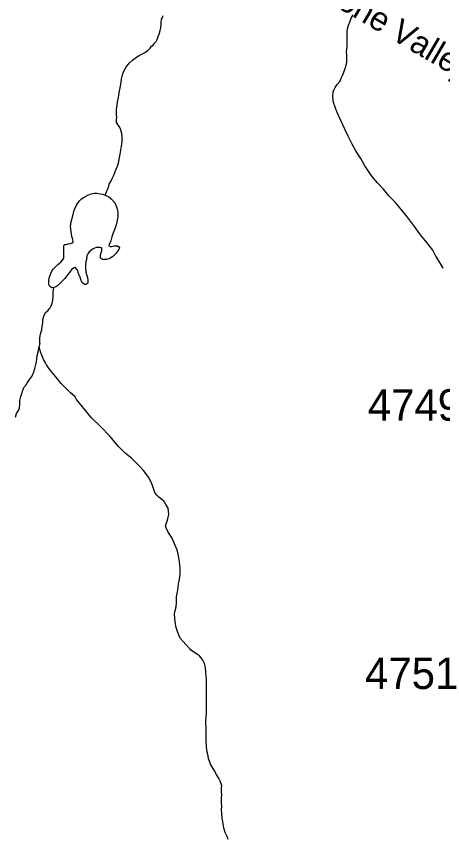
# Model space of a CAD drawing. Extents: x 2001466 to 2224147, y 644118 to 847247.
# Drawn here: x 2068297 to 2069996, y 672647 to 675928 of the extents above; entities that cross this region are included whole.
import ezdxf

# ---------------------------------------------------------------- set-up
doc = ezdxf.new("R2010")
doc.units = 0
for name, color, linetype in [('Exist Hydrographic Misc Water Feature', 7, 'Continuous'), ('Exist Road Non-System Type 51 Label', 7, 'Continuous'), ('Exist Road Secondary Type 51 Number Label', 7, 'Continuous')]:
    doc.layers.add(name, color=color, linetype=linetype)

msp = doc.modelspace()

# ---------------------------------------------------------------- linework, layer by layer
at = {"layer": 'Exist Hydrographic Misc Water Feature'}
msp.add_line((2068389.9, 674624.9), (2068387.2, 674613.2), dxfattribs=at)
for points in [[(2069998.9, 674924.2), (2069985, 674947.7), (2069969, 674972), (2069956.9, 674995.8), (2069938.9, 675020), (2069908.5, 675057.9), (2069880.4, 675095.8), (2069856.4, 675127.8), (2069834.3, 675155.5), (2069806.6, 675187.8), (2069782.4, 675213.3), (2069760.3, 675239.4), (2069736.7, 675265.3), (2069714.1, 675291.4), (2069700.4, 675311.3), (2069686.2, 675333.3), (2069670, 675361.3), (2069652.2, 675389.2), (2069636, 675419.2), (2069620, 675451.3), (2069606.1, 675478.9), (2069590.1, 675513), (2069575.9, 675545.2), (2069567.9, 675567.1), (2069561.6, 675585), (2069558.1, 675609.1), (2069559.7, 675627.1), (2069563.8, 675637), (2069567.7, 675644.9), (2069575.7, 675657.1), (2069585.8, 675669), (2069593.5, 675685.2), (2069597.9, 675695.2), (2069607.7, 675721.2), (2069613.8, 675745), (2069613.8, 675755.2), (2069613.8, 675773), (2069613.4, 675788.9), (2069615.5, 675808.9), (2069615.5, 675827.1), (2069615.1, 675845), (2069615.5, 675857.2), (2069615.3, 675868.9), (2069617.5, 675879.1), (2069621, 675893.2), (2069627.2, 675908.9), (2069631.3, 675921.3), (2069639.1, 675935.1)], [(2068698.5, 675501.3), (2068696, 675505.3), (2068696, 675515.4), (2068696.4, 675527.6), (2068696, 675535.3), (2068696, 675545.5), (2068696, 675555.2), (2068696.2, 675559.2), (2068698.1, 675573.5), (2068700.1, 675587.5), (2068703.8, 675605.5), (2068706.1, 675623.4), (2068709.8, 675643.5), (2068713.9, 675665.3), (2068715.7, 675679.6), (2068719.8, 675695.6), (2068723.9, 675707.5), (2068729.7, 675719.6), (2068735.6, 675729.3), (2068747.7, 675743.3), (2068759.6, 675753.7), (2068769.9, 675761.4), (2068783.8, 675771.4), (2068799.6, 675779.6), (2068811.7, 675785.5), (2068821.5, 675793.7), (2068829.7, 675801.4), (2068835.7, 675809.4), (2068841.4, 675813.8), (2068847.4, 675821.4), (2068853.5, 675827.8), (2068857.4, 675835.7), (2068861.5, 675847.7), (2068865.8, 675857.6), (2068869.3, 675871.7), (2068871.4, 675877.9), (2068873.6, 675891.7), (2068873.4, 675903.5), (2068875.5, 675917.8), (2068877.3, 675921.5), (2068881.4, 675931.5)], [(2068650.7, 675215.3), (2068658.7, 675235.5), (2068660.6, 675241.4), (2068664.9, 675251.3), (2068666.7, 675259.5), (2068672.7, 675269.6), (2068678.8, 675281.6), (2068684.6, 675295.4), (2068688.9, 675305.7), (2068694.4, 675319.4), (2068700.5, 675335.5), (2068704.6, 675349.5), (2068706.7, 675359.3), (2068710.4, 675379.4), (2068714.5, 675403.6), (2068716.1, 675411.4), (2068718.4, 675429.3), (2068718.4, 675439.5), (2068718.4, 675449.6), (2068716.3, 675461.2), (2068714.3, 675469.3), (2068712.2, 675477.3), (2068706.3, 675489.5), (2068698.5, 675501.3)], [(2068445.3, 674847.3), (2068437.7, 674846.9), (2068433.4, 674849.1), (2068429.3, 674851), (2068425.2, 674859.3), (2068425.4, 674865), (2068425.4, 674875.1), (2068427.4, 674884.9), (2068429.3, 674893.2), (2068433.4, 674903), (2068437.3, 674913), (2068443.2, 674921), (2068451.4, 674929.1), (2068457.4, 674935.1), (2068463.1, 674941.1), (2068469.2, 674945.1), (2068472.9, 674949), (2068479.1, 674955), (2068483, 674961.2), (2068485.4, 674965), (2068485, 674971.1), (2068485.4, 674983.2), (2068485.2, 674989.3), (2068485.2, 674997), (2068485.2, 675003.1), (2068485.2, 675007.2), (2068485.4, 675011.2), (2068485.2, 675015.3), (2068489.3, 675019.1), (2068495.3, 675019), (2068503.3, 675021.1), (2068513.3, 675023.2), (2068519.1, 675025.1), (2068522.8, 675029), (2068521.1, 675039), (2068517, 675051), (2068515, 675071.2), (2068512.7, 675091.4), (2068515, 675109.3), (2068521.1, 675133.1), (2068526.9, 675155.4), (2068536.7, 675179), (2068547, 675191.3), (2068556.6, 675201.1), (2068567.1, 675207.3), (2068580.6, 675215.3), (2068594.7, 675221.3), (2068606.6, 675223.2), (2068618.5, 675223.4), (2068630.6, 675221.6), (2068640.9, 675219.2), (2068650.7, 675215.3)], [(2068650.7, 675215.3), (2068664.7, 675209.5), (2068674.9, 675201.5), (2068688.7, 675185.6), (2068695, 675169.6), (2068699.1, 675155.6), (2068700.8, 675145.6), (2068700.8, 675127.4), (2068698.7, 675115.5), (2068695.2, 675101.5), (2068688.9, 675081.7), (2068680.9, 675061.4), (2068677.2, 675049.5), (2068673.1, 675033.4), (2068666.9, 675019.4), (2068665.1, 675013.5), (2068671.2, 675011.4), (2068677.2, 675011.3), (2068686.8, 675013.5), (2068695, 675013.5), (2068699.1, 675013.7), (2068704.9, 675009.6), (2068707.1, 675005.6), (2068704.9, 674999.4), (2068701, 674993.5), (2068693.4, 674983.3), (2068689.3, 674979.5), (2068681.1, 674971.4), (2068674.9, 674967.4), (2068669.2, 674963.4), (2068655.2, 674959.5), (2068647.2, 674959.5), (2068639.2, 674959.5), (2068635.1, 674961.3), (2068631.2, 674965.5), (2068631.2, 674973.3), (2068632.9, 674983.5), (2068637.2, 674993.5), (2068636.8, 675001.6), (2068635.3, 675005.5), (2068628.8, 675007.3), (2068622.8, 675007.4), (2068614.8, 675007.4), (2068603.1, 675001.4), (2068597, 674997.5), (2068587.2, 674989.3), (2068581.2, 674981.3), (2068577.3, 674973.3), (2068575.5, 674959.4), (2068573.2, 674951.2), (2068571.4, 674937.3), (2068571.4, 674925.5), (2068573.4, 674909.4), (2068575.3, 674899.4), (2068579.6, 674887.4), (2068581.4, 674875.4), (2068581.2, 674871.4), (2068581.2, 674867.3), (2068579.4, 674863.5), (2068573.6, 674859.1), (2068567.7, 674859.2), (2068561.3, 674865.4), (2068557.4, 674869.3), (2068553.5, 674879.2), (2068551.3, 674889.3), (2068547.2, 674897.1), (2068543.3, 674907.1), (2068541.2, 674915.1), (2068537.3, 674919.3), (2068533.2, 674925.2), (2068529.1, 674927.1), (2068523.4, 674925.1), (2068517.2, 674921.2), (2068507.6, 674907.2), (2068501.2, 674899.3), (2068493, 674889.2), (2068489.1, 674883.3), (2068483.4, 674877.2), (2068475.4, 674869.1), (2068467.2, 674861), (2068461.5, 674855), (2068453.7, 674850.9), (2068445.3, 674847.3)], [(2068389.9, 674624.9), (2068390.1, 674633), (2068389.9, 674645.2), (2068391.5, 674655.1), (2068393.6, 674666.9), (2068397.7, 674679.3), (2068399.7, 674693.2), (2068401.6, 674705.1), (2068401.8, 674713.2), (2068403.6, 674725.1), (2068407.7, 674737), (2068413.7, 674749.1), (2068421.5, 674755.2), (2068427.4, 674763.2), (2068431.5, 674767), (2068435.4, 674775), (2068439.3, 674783.3), (2068441.6, 674797.2), (2068443.4, 674813.1), (2068443.6, 674828.9), (2068445.3, 674847.3)], [(2068304.6, 674356.8), (2068308.3, 674366.8), (2068310.1, 674383.1), (2068310.3, 674396.9), (2068314.2, 674412.9), (2068317.9, 674424.9), (2068322.4, 674438.9), (2068326.1, 674448.8), (2068336.4, 674461.1), (2068339.9, 674467), (2068346.2, 674477), (2068356.3, 674490.9), (2068362, 674501), (2068365.9, 674510.9), (2068370, 674524.9), (2068374.3, 674540.9), (2068375.9, 674551.2), (2068377.8, 674565.1), (2068379.8, 674577), (2068384.2, 674597), (2068387.2, 674613.2)], [(2068535.9, 674401.2), (2068530.4, 674411.4), (2068520.1, 674421.4), (2068512.1, 674427.1), (2068500.2, 674439.1), (2068490.4, 674449.1), (2068482.4, 674457.2), (2068474.4, 674465.3), (2068468, 674473.2), (2068459.8, 674483.3), (2068445.9, 674501.2), (2068431.9, 674517.1), (2068421.9, 674531.2), (2068416.1, 674539), (2068411.8, 674547), (2068404, 674561.1), (2068400.1, 674571.1), (2068393.8, 674587), (2068389.9, 674601), (2068387.2, 674613.2)], [(2069141.2, 672646.9), (2069137.3, 672658.9), (2069129.3, 672674.7), (2069125.2, 672688.7), (2069120.9, 672706.8), (2069119.1, 672718.8), (2069117, 672730.9), (2069115.2, 672750.7), (2069114.8, 672766.9), (2069115.2, 672778.7), (2069114.8, 672794.9), (2069114.8, 672812.7), (2069115.2, 672824.9), (2069115, 672836.7), (2069114.8, 672850.9), (2069115.2, 672862.6), (2069108.8, 672879), (2069102.7, 672892.9), (2069094.9, 672906.7), (2069086.5, 672920.9), (2069078.7, 672934.6), (2069070.9, 672946.8), (2069067, 672958.7), (2069062.7, 672968.7), (2069060.8, 672980.7), (2069056.5, 673000.9), (2069054.7, 673020.6), (2069052.6, 673038.8), (2069052.6, 673066.8), (2069052.6, 673084.6), (2069052.2, 673120.8), (2069054.3, 673150.5), (2069054.3, 673186.6), (2069054.1, 673218.6), (2069054.3, 673262.4), (2069054.1, 673286.8), (2069052, 673312.7), (2069050.2, 673332.4), (2069046.1, 673348.4), (2069039.9, 673362.3), (2069031.7, 673372.5), (2069026, 673378.6), (2069018, 673384.3), (2068992.1, 673402.4), (2068989.9, 673406.4), (2068972, 673424.6), (2068961.6, 673436.3), (2068949.9, 673450.2), (2068940, 673472.4), (2068933.5, 673492.4), (2068930, 673514.1), (2068927.5, 673546.1), (2068929.6, 673560.4), (2068933.7, 673574.4), (2068935.3, 673590.3), (2068935.5, 673614.2), (2068939.4, 673634.3), (2068941.7, 673650.2), (2068943.3, 673666.2), (2068947.2, 673684.2), (2068949.7, 673706.2), (2068949.5, 673730.1), (2068947, 673754.4), (2068943.3, 673778.1), (2068937.2, 673802.2), (2068927.1, 673826.4), (2068917.3, 673848.2), (2068901.3, 673872.1), (2068893.1, 673889.9), (2068891.2, 673895.9), (2068893.3, 673906.1), (2068899, 673920.3), (2068901.1, 673932.2), (2068904.8, 673942.1), (2068902.9, 673956.2), (2068901.1, 673968.3), (2068892.7, 673982.1), (2068885.1, 673994.2), (2068876.9, 674001.9), (2068865, 674012.2), (2068856.6, 674020), (2068849, 674030.1), (2068844.5, 674042.1), (2068838.8, 674058), (2068832.8, 674073.9), (2068822.8, 674092.1), (2068812.7, 674105.8), (2068802.7, 674117.8), (2068788.9, 674133.7), (2068772.9, 674149.9), (2068756.3, 674165.8), (2068730.7, 674187.6), (2068702.6, 674215.7), (2068670.2, 674253.5), (2068632.3, 674293.7), (2068596.4, 674327.6), (2068535.9, 674401.2)], [(2068292.5, 674331), (2068296.6, 674345), (2068304.6, 674356.8)]]:
    msp.add_lwpolyline(points, dxfattribs=at)

# ---------------------------------------------------------------- texts
at = {"layer": 'Exist Road Non-System Type 51 Label'}
msp.add_text('Stone Valley Ct.', height=95, rotation=329.6196, dxfattribs=at).set_placement((2069467.4, 676027.3))
at = {"layer": 'Exist Road Secondary Type 51 Number Label'}
for s, p in [('4749', (2069698, 674316.9)), ('4751', (2069687, 673247.1))]:
    msp.add_text(s, height=125, dxfattribs=at).set_placement(p)

doc.saveas('drawing.dxf')
